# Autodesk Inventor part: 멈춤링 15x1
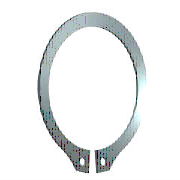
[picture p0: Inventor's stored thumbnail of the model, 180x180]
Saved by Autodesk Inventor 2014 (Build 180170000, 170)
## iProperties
Created: 2015-09
Part Number: 멈춤링 15x1
Material: 강철, 연강
Description: 리테이닝 링(C형)
Document SubType Name: Modeling
Standard: KS B 1336
Designer: mm
Standards Organization: KS
Language: ko-KR
Size Designation: 15 x 1
Categories: <MemberInstance><Categories><Category DisplayName="샤프트 부품" InternalName="7f7aeb1f-a693-4053-b835-cee3144e0d98" Mnemonic="SHFT"><Category DisplayName="써클립" Inter
Density: 1 g/cm^3
Appearance: 파란색 - 벽 페인트 - 광택
IsCustomPart: 1
Author: mduedu
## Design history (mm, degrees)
sketch "스케치1"
  geometry: L1 (-6, 0)-(6, 0) reference; L2 (0, 20.189)-(0, -80.536) reference; L3 (-48.09, 0)-(48.09, 0) reference; L4 (-0.425, -14.637)-(-0.425, -18.137); L5 (-0.425, -6.54)-(-0.425, -13.29); L6 (-2.795, 2.1)-(3.672, 2.1); L7 (0.425, -6.54)-(0.425, -13.29); L8 (0.425, -14.637)-(0.425, -18.137); C1 r 0.85 at (-1.7, -16.283); C2 r 0.85 at (1.7, -16.283); A1 r 7.15 centre (0, -7.5) between (0.425, -14.637) and (-0.425, -14.637); A2 r 9.075 centre (0, -6.975) between (4.291, -14.971) and (-4.291, -14.971); A3 r 10.646 centre (0, -7.5) between (-2.023, -17.952) and (-0.425, -18.137); A4 r 1.7 centre (-1.7, -16.283) between (-3.397, -16.376) and (-2.023, -17.952); A5 r 1.7 centre (-5.095, -16.469) between (-3.397, -16.376) and (-4.291, -14.971); A6 r 1.7 centre (5.095, -16.469) between (4.291, -14.971) and (3.397, -16.376); A7 r 1.7 centre (1.7, -16.283) between (2.023, -17.952) and (3.397, -16.376); A8 r 10.646 centre (0, -7.5) between (0.425, -18.137) and (2.023, -17.952)
  constraints: 16 point on circle, 12 end point, 10 centre point, 9 symmetric about line, 5 point on line, 4 tangent, 3 coincident, 2 horizontal, 1 perpendicular, 1 vertical, 5 other
  dimensions: "d0" = 14.3 diameter of A1 (= ND); "d1" = 3.5 distance of L4.end L4.start (= SRB2); "d6" = 0.425 distance between parallel lines of L2 L5 (= 0.25 x SD5); "d7" = 2.1 distance between parallel lines of L6 L3 (= SRB1); "d8" = 0.525 distance of A1.centre A2.centre (= 0.25 x SRB1); "d9" = 1.7 radius of A4 (= SD5); "d10" = 1.7 radius of A5 (= SD5); "d11" = 1.275 distance from line of L4 A4.centre (= 0.75 x SD5); "d12" = 1.7 diameter of C1 (= SD5); "d13" = 1.7 diameter of C2 (= SD5); "d14" = 7.5 distance from line of A1.centre L1 (= 0.5 x WD)
extrude "본체" new body sketch "스케치1" distance "d2" = 1 (= SD); taper "d3" = 0 deg
workaxis "Work Axis1"
workplane "Work Plane1"
body "Solid1"
other parameters: "WD" = 15 (= WDMIN) [user parameter; used in 1 equation term], "SD" = 1 [user parameter; used in 1 equation term], "SRB1" = 2.1 [user parameter; used in 2 equation terms], "ND" = 14.3 [user parameter; used in 1 equation term], "SRB2" = 3.5 [user parameter; used in 1 equation term], "SD5" = 1.7 [user parameter; used in 6 equation terms], "d15" = 0, "d16" = 0, "d17" = 0, "d41" = 0, "d42" = 0, "WDMIN" = 15 [user parameter; used in 1 equation term], "SD3" = 13.8 [user parameter], "WDMAX" = 16 [user parameter]
